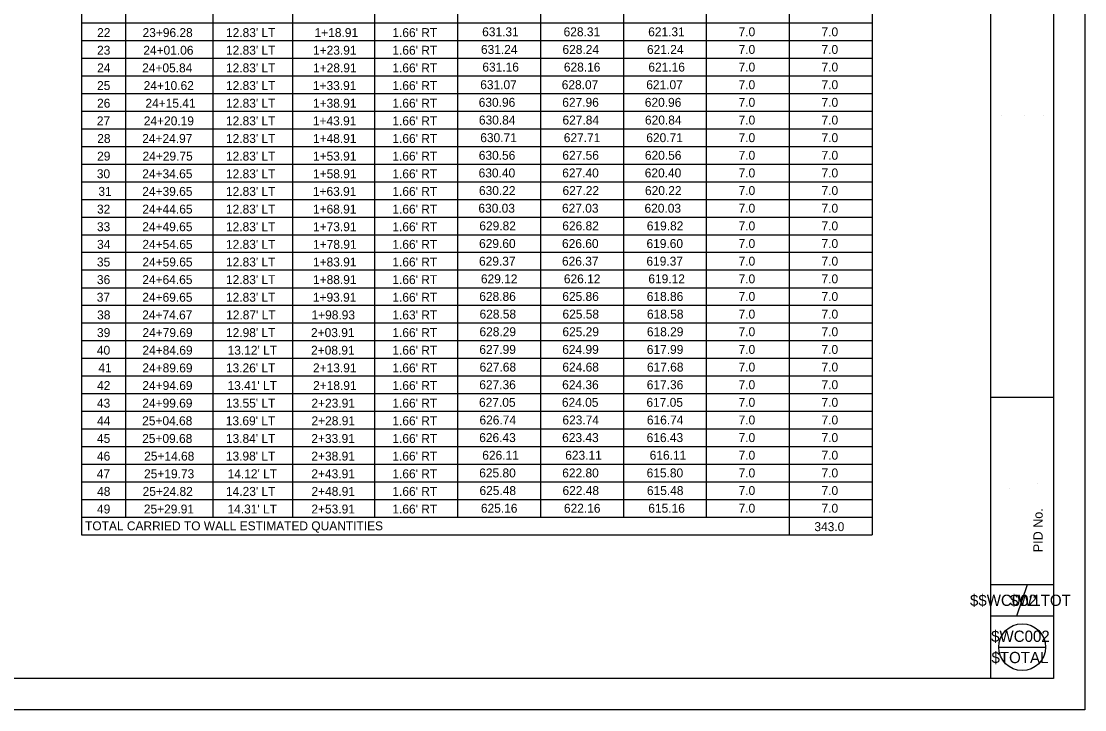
# Model space of a CAD drawing. Extents: x -0.2 to 33.8, y -0.1 to 21.9.
# Drawn here: x 16.78 to 33.78, y -0.13 to 10.88 of the extents above; entities that cross this region are included whole.
import ezdxf

# ---------------------------------------------------------------- set-up
doc = ezdxf.new("R2010")
doc.units = 0
for name, color, linetype in [('BR_P_Gen_Text', 7, 'Continuous'), ('SH_Border', 7, 'Continuous'), ('SH_Cut_Line', 7, 'Continuous'), ('SH_Data', 7, 'Continuous')]:
    doc.layers.add(name, color=color, linetype=linetype)

msp = doc.modelspace()

# ---------------------------------------------------------------- linework, layer by layer
at = {"layer": 'BR_P_Gen_Text'}
for p, q in [((17.738, 19.836), (17.738, 2.667)), ((30.379, 19.836), (30.379, 2.667)), ((18.444, 19.554), (18.444, 2.949)), ((19.84, 19.554), (19.84, 2.949)), ((21.11, 19.554), (21.11, 2.949)), ((22.422, 19.554), (22.422, 2.949)), ((23.748, 19.554), (23.748, 2.949)), ((25.074, 19.554), (25.074, 2.949)), ((26.4, 19.554), (26.4, 2.949)), ((27.726, 19.554), (27.726, 2.949)), ((29.052, 19.554), (29.052, 2.667)), ((17.738, 10.85), (30.379, 10.85)), ((17.738, 10.567), (30.379, 10.567)), ((17.738, 10.285), (30.379, 10.285)), ((17.738, 10.003), (30.379, 10.003)), ((17.738, 9.721), (30.379, 9.721)), ((17.738, 9.439), (30.379, 9.439)), ((17.738, 9.157), (30.379, 9.157)), ((17.738, 8.875), (30.379, 8.875)), ((17.738, 8.592), (30.379, 8.592)), ((17.738, 8.31), (30.379, 8.31)), ((17.738, 8.028), (30.379, 8.028)), ((17.738, 7.746), (30.379, 7.746)), ((17.738, 7.464), (30.379, 7.464)), ((17.738, 7.182), (30.379, 7.182)), ((17.738, 6.9), (30.379, 6.9)), ((17.738, 6.617), (30.379, 6.617)), ((17.738, 6.335), (30.379, 6.335)), ((17.738, 6.053), (30.379, 6.053)), ((17.738, 5.771), (30.379, 5.771)), ((17.738, 5.489), (30.379, 5.489)), ((17.738, 5.207), (30.379, 5.207)), ((17.738, 4.924), (30.379, 4.924)), ((17.738, 4.642), (30.379, 4.642)), ((17.738, 4.36), (30.379, 4.36)), ((17.738, 4.078), (30.379, 4.078)), ((17.738, 3.796), (30.379, 3.796)), ((17.738, 3.514), (30.379, 3.514)), ((17.738, 3.232), (30.379, 3.232)), ((17.738, 2.949), (30.379, 2.949)), ((17.738, 2.667), (30.379, 2.667))]:
    msp.add_line(p, q, dxfattribs=at)
at = {"layer": 'SH_Border'}
for p, q in [((32.275, 0.368), (32.275, 21.368)), ((32.275, 4.868), (33.275, 4.868)), ((32.275, 1.868), (33.275, 1.868)), ((32.692, 1.368), (32.859, 1.868)), ((32.275, 1.368), (33.275, 1.368))]:
    msp.add_line(p, q, dxfattribs=at)
msp.add_lwpolyline([(1.775, 21.368), (33.275, 21.368), (33.275, 0.368), (1.775, 0.368)], close=True, dxfattribs=at)
at = {"layer": 'SH_Cut_Line'}
msp.add_lwpolyline([(-0.225, 21.868), (33.775, 21.868), (33.775, -0.132), (-0.225, -0.132)], close=True, dxfattribs=at)
at = {"layer": 'SH_Data'}
for p, q in [((32.442, 9.368), (32.442, 9.368)), ((32.817, 9.368), (32.817, 9.368)), ((33.109, 9.368), (33.109, 9.368)), ((33.025, 3.486), (33.025, 3.486)), ((32.575, 3.398), (32.575, 3.398)), ((32.525, 1.618), (32.525, 1.618)), ((33.025, 1.618), (33.025, 1.618)), ((32.4, 0.868), (33.15, 0.868)), ((32.775, 0.953), (32.775, 0.953)), ((32.775, 0.613), (32.775, 0.613))]:
    msp.add_line(p, q, dxfattribs=at)
msp.add_circle((32.775, 0.868), 0.375, dxfattribs=at)

# ---------------------------------------------------------------- texts
at = {"layer": 'BR_P_Gen_Text'}
for s, height, p in [('22', 0.1428, (17.988, 10.624)), ('23+96.28', 0.1428, (18.714, 10.624)), ("12.83' LT", 0.1428, (20.048, 10.624)), ('1+18.91', 0.1428, (21.464, 10.624)), ("1.66' RT", 0.1428, (22.708, 10.624)), ('631.31', 0.1428, (24.143, 10.637)), ('628.31', 0.1428, (25.445, 10.637)), ('621.31', 0.1428, (26.797, 10.637)), ('7.0', 0.1428, (28.242, 10.637)), ('7.0', 0.1428, (29.568, 10.637)), ('23', 0.1428, (17.987, 10.342)), ('24+01.06', 0.1428, (18.726, 10.342)), ("12.83' LT", 0.1428, (20.048, 10.342)), ('1+23.91', 0.1428, (21.439, 10.342)), ("1.66' RT", 0.1428, (22.708, 10.342)), ('631.24', 0.1428, (24.124, 10.355)), ('628.24', 0.1428, (25.427, 10.355)), ('621.24', 0.1428, (26.778, 10.355)), ('7.0', 0.1428, (28.242, 10.355)), ('7.0', 0.1428, (29.568, 10.355)), ('24', 0.1428, (17.989, 10.06)), ('24+05.84', 0.1428, (18.708, 10.06)), ("12.83' LT", 0.1428, (20.048, 10.06)), ('1+28.91', 0.1428, (21.44, 10.06)), ("1.66' RT", 0.1428, (22.708, 10.06)), ('631.16', 0.1428, (24.146, 10.073)), ('628.16', 0.1428, (25.449, 10.073)), ('621.16', 0.1428, (26.8, 10.073)), ('7.0', 0.1428, (28.242, 10.073)), ('7.0', 0.1428, (29.568, 10.073)), ('25', 0.1428, (17.987, 9.777)), ('24+10.62', 0.1428, (18.732, 9.777)), ("12.83' LT", 0.1428, (20.048, 9.777)), ('1+33.91', 0.1428, (21.437, 9.777)), ("1.66' RT", 0.1428, (22.708, 9.777)), ('631.07', 0.1428, (24.112, 9.791)), ('628.07', 0.1428, (25.415, 9.791)), ('621.07', 0.1428, (26.766, 9.791)), ('7.0', 0.1428, (28.242, 9.791)), ('7.0', 0.1428, (29.568, 9.791)), ('26', 0.1428, (17.987, 9.495)), ('24+15.41', 0.1428, (18.76, 9.495)), ("12.83' LT", 0.1428, (20.048, 9.495)), ('1+38.91', 0.1428, (21.438, 9.495)), ("1.66' RT", 0.1428, (22.708, 9.495)), ('630.96', 0.1428, (24.088, 9.509)), ('627.96', 0.1428, (25.424, 9.509)), ('620.96', 0.1428, (26.743, 9.509)), ('7.0', 0.1428, (28.242, 9.509)), ('7.0', 0.1428, (29.568, 9.509)), ('27', 0.1428, (17.984, 9.213)), ('24+20.19', 0.1428, (18.734, 9.213)), ("12.83' LT", 0.1428, (20.048, 9.213)), ('1+43.91', 0.1428, (21.437, 9.213)), ("1.66' RT", 0.1428, (22.708, 9.213)), ('630.84', 0.1428, (24.091, 9.226)), ('627.84', 0.1428, (25.427, 9.226)), ('620.84', 0.1428, (26.746, 9.226)), ('7.0', 0.1428, (28.242, 9.226)), ('7.0', 0.1428, (29.568, 9.226)), ('28', 0.1428, (17.99, 8.931)), ('24+24.97', 0.1428, (18.709, 8.931)), ("12.83' LT", 0.1428, (20.048, 8.931)), ('1+48.91', 0.1428, (21.438, 8.931)), ("1.66' RT", 0.1428, (22.708, 8.931)), ('630.71', 0.1428, (24.113, 8.944)), ('627.71', 0.1428, (25.448, 8.944)), ('620.71', 0.1428, (26.767, 8.944)), ('7.0', 0.1428, (28.242, 8.944)), ('7.0', 0.1428, (29.568, 8.944)), ('29', 0.1428, (17.988, 8.649)), ('24+29.75', 0.1428, (18.714, 8.649)), ("12.83' LT", 0.1428, (20.048, 8.649)), ('1+53.91', 0.1428, (21.438, 8.649)), ("1.66' RT", 0.1428, (22.708, 8.649)), ('630.56', 0.1428, (24.089, 8.662)), ('627.56', 0.1428, (25.425, 8.662)), ('620.56', 0.1428, (26.744, 8.662)), ('7.0', 0.1428, (28.242, 8.662)), ('7.0', 0.1428, (29.568, 8.662)), ('30', 0.1428, (17.983, 8.367)), ('24+34.65', 0.1428, (18.71, 8.367)), ("12.83' LT", 0.1428, (20.048, 8.367)), ('1+58.91', 0.1428, (21.439, 8.367)), ("1.66' RT", 0.1428, (22.708, 8.367)), ('630.40', 0.1428, (24.087, 8.38)), ('627.40', 0.1428, (25.423, 8.38)), ('620.40', 0.1428, (26.742, 8.38)), ('7.0', 0.1428, (28.242, 8.38)), ('7.0', 0.1428, (29.568, 8.38)), ('31', 0.1428, (18.008, 8.085)), ('24+39.65', 0.1428, (18.71, 8.085)), ("12.83' LT", 0.1428, (20.048, 8.085)), ('1+63.91', 0.1428, (21.437, 8.085)), ("1.66' RT", 0.1428, (22.708, 8.085)), ('630.22', 0.1428, (24.092, 8.098)), ('627.22', 0.1428, (25.427, 8.098)), ('620.22', 0.1428, (26.746, 8.098)), ('7.0', 0.1428, (28.242, 8.098)), ('7.0', 0.1428, (29.568, 8.098)), ('32', 0.1428, (17.986, 7.802)), ('24+44.65', 0.1428, (18.711, 7.802)), ("12.83' LT", 0.1428, (20.048, 7.802)), ('1+68.91', 0.1428, (21.438, 7.802)), ("1.66' RT", 0.1428, (22.708, 7.802)), ('630.03', 0.1428, (24.083, 7.816)), ('627.03', 0.1428, (25.419, 7.816)), ('620.03', 0.1428, (26.738, 7.816)), ('7.0', 0.1428, (28.242, 7.816)), ('7.0', 0.1428, (29.568, 7.816)), ('33', 0.1428, (17.985, 7.52)), ('24+49.65', 0.1428, (18.71, 7.52)), ("12.83' LT", 0.1428, (20.048, 7.52)), ('1+73.91', 0.1428, (21.439, 7.52)), ("1.66' RT", 0.1428, (22.708, 7.52)), ('629.82', 0.1428, (24.098, 7.534)), ('626.82', 0.1428, (25.424, 7.534)), ('619.82', 0.1428, (26.775, 7.534)), ('7.0', 0.1428, (28.242, 7.534)), ('7.0', 0.1428, (29.568, 7.534)), ('34', 0.1428, (17.987, 7.238)), ('24+54.65', 0.1428, (18.711, 7.238)), ("12.83' LT", 0.1428, (20.048, 7.238)), ('1+78.91', 0.1428, (21.44, 7.238)), ("1.66' RT", 0.1428, (22.708, 7.238)), ('629.60', 0.1428, (24.094, 7.251)), ('626.60', 0.1428, (25.42, 7.251)), ('619.60', 0.1428, (26.77, 7.251)), ('7.0', 0.1428, (28.242, 7.251)), ('7.0', 0.1428, (29.568, 7.251)), ('35', 0.1428, (17.985, 6.956)), ('24+59.65', 0.1428, (18.711, 6.956)), ("12.83' LT", 0.1428, (20.048, 6.956)), ('1+83.91', 0.1428, (21.438, 6.956)), ("1.66' RT", 0.1428, (22.708, 6.956)), ('629.37', 0.1428, (24.093, 6.969)), ('626.37', 0.1428, (25.419, 6.969)), ('619.37', 0.1428, (26.769, 6.969)), ('7.0', 0.1428, (28.242, 6.969)), ('7.0', 0.1428, (29.568, 6.969)), ('36', 0.1428, (17.985, 6.674)), ('24+64.65', 0.1428, (18.71, 6.674)), ("12.83' LT", 0.1428, (20.048, 6.674)), ('1+88.91', 0.1428, (21.439, 6.674)), ("1.66' RT", 0.1428, (22.708, 6.674)), ('629.12', 0.1428, (24.123, 6.687)), ('626.12', 0.1428, (25.449, 6.687)), ('619.12', 0.1428, (26.8, 6.687)), ('7.0', 0.1428, (28.242, 6.687)), ('7.0', 0.1428, (29.568, 6.687)), ('37', 0.1428, (17.982, 6.392)), ('24+69.65', 0.1428, (18.71, 6.392)), ("12.83' LT", 0.1428, (20.048, 6.392)), ('1+93.91', 0.1428, (21.437, 6.392)), ("1.66' RT", 0.1428, (22.708, 6.392)), ('628.86', 0.1428, (24.097, 6.405)), ('625.86', 0.1428, (25.424, 6.405)), ('618.86', 0.1428, (26.774, 6.405)), ('7.0', 0.1428, (28.242, 6.405)), ('7.0', 0.1428, (29.568, 6.405)), ('38', 0.1428, (17.988, 6.11)), ('24+74.67', 0.1428, (18.709, 6.11)), ("12.87' LT", 0.1428, (20.05, 6.11)), ('1+98.93', 0.1428, (21.415, 6.11)), ("1.63' RT", 0.1428, (22.708, 6.11)), ('628.58', 0.1428, (24.101, 6.123)), ('625.58', 0.1428, (25.427, 6.123)), ('618.58', 0.1428, (26.777, 6.123)), ('7.0', 0.1428, (28.242, 6.123)), ('7.0', 0.1428, (29.568, 6.123)), ('39', 0.1428, (17.986, 5.827)), ('24+79.69', 0.1428, (18.712, 5.827)), ("12.98' LT", 0.1428, (20.048, 5.827)), ('2+03.91', 0.1428, (21.407, 5.827)), ("1.66' RT", 0.1428, (22.708, 5.827)), ('628.29', 0.1428, (24.1, 5.841)), ('625.29', 0.1428, (25.426, 5.841)), ('618.29', 0.1428, (26.776, 5.841)), ('7.0', 0.1428, (28.242, 5.841)), ('7.0', 0.1428, (29.568, 5.841)), ('40', 0.1428, (17.984, 5.545)), ('24+84.69', 0.1428, (18.712, 5.545)), ("13.12' LT", 0.1428, (20.074, 5.545)), ('2+08.91', 0.1428, (21.408, 5.545)), ("1.66' RT", 0.1428, (22.708, 5.545)), ('627.99', 0.1428, (24.098, 5.558)), ('624.99', 0.1428, (25.423, 5.558)), ('617.99', 0.1428, (26.775, 5.558)), ('7.0', 0.1428, (28.242, 5.558)), ('7.0', 0.1428, (29.568, 5.558)), ('41', 0.1428, (18.008, 5.263)), ('24+89.69', 0.1428, (18.711, 5.263)), ("13.26' LT", 0.1428, (20.047, 5.263)), ('2+13.91', 0.1428, (21.439, 5.263)), ("1.66' RT", 0.1428, (22.708, 5.263)), ('627.68', 0.1428, (24.101, 5.276)), ('624.68', 0.1428, (25.425, 5.276)), ('617.68', 0.1428, (26.777, 5.276)), ('7.0', 0.1428, (28.242, 5.276)), ('7.0', 0.1428, (29.568, 5.276)), ('42', 0.1428, (17.987, 4.981)), ('24+94.69', 0.1428, (18.711, 4.981)), ("13.41' LT", 0.1428, (20.072, 4.981)), ('2+18.91', 0.1428, (21.44, 4.981)), ("1.66' RT", 0.1428, (22.708, 4.981)), ('627.36', 0.1428, (24.097, 4.994)), ('624.36', 0.1428, (25.422, 4.994)), ('617.36', 0.1428, (26.774, 4.994)), ('7.0', 0.1428, (28.242, 4.994)), ('7.0', 0.1428, (29.568, 4.994)), ('43', 0.1428, (17.985, 4.699)), ('24+99.69', 0.1428, (18.71, 4.699)), ("13.55' LT", 0.1428, (20.047, 4.699)), ('2+23.91', 0.1428, (21.414, 4.699)), ("1.66' RT", 0.1428, (22.708, 4.699)), ('627.05', 0.1428, (24.093, 4.712)), ('624.05', 0.1428, (25.418, 4.712)), ('617.05', 0.1428, (26.769, 4.712)), ('7.0', 0.1428, (28.242, 4.712)), ('7.0', 0.1428, (29.568, 4.712)), ('44', 0.1428, (17.987, 4.417)), ('25+04.68', 0.1428, (18.708, 4.417)), ("13.69' LT", 0.1428, (20.045, 4.417)), ('2+28.91', 0.1428, (21.415, 4.417)), ("1.66' RT", 0.1428, (22.708, 4.417)), ('626.74', 0.1428, (24.1, 4.43)), ('623.74', 0.1428, (25.426, 4.43)), ('616.74', 0.1428, (26.776, 4.43)), ('7.0', 0.1428, (28.242, 4.43)), ('7.0', 0.1428, (29.568, 4.43)), ('45', 0.1428, (17.986, 4.134)), ('25+09.68', 0.1428, (18.708, 4.134)), ("13.84' LT", 0.1428, (20.047, 4.134)), ('2+33.91', 0.1428, (21.412, 4.134)), ("1.66' RT", 0.1428, (22.708, 4.134)), ('626.43', 0.1428, (24.096, 4.148)), ('623.43', 0.1428, (25.422, 4.148)), ('616.43', 0.1428, (26.772, 4.148)), ('7.0', 0.1428, (28.242, 4.148)), ('7.0', 0.1428, (29.568, 4.148)), ('46', 0.1428, (17.985, 3.852)), ('25+14.68', 0.1428, (18.74, 3.852)), ("13.98' LT", 0.1428, (20.046, 3.852)), ('2+38.91', 0.1428, (21.413, 3.852)), ("1.66' RT", 0.1428, (22.708, 3.852)), ('626.11', 0.1428, (24.145, 3.866)), ('623.11', 0.1428, (25.471, 3.866)), ('616.11', 0.1428, (26.821, 3.866)), ('7.0', 0.1428, (28.242, 3.866)), ('7.0', 0.1428, (29.568, 3.866)), ('47', 0.1428, (17.983, 3.57)), ('25+19.73', 0.1428, (18.738, 3.57)), ("14.12' LT", 0.1428, (20.074, 3.57)), ('2+43.91', 0.1428, (21.413, 3.57)), ("1.66' RT", 0.1428, (22.708, 3.57)), ('625.80', 0.1428, (24.096, 3.583)), ('622.80', 0.1428, (25.423, 3.583)), ('615.80', 0.1428, (26.772, 3.583)), ('7.0', 0.1428, (28.242, 3.583)), ('7.0', 0.1428, (29.568, 3.583)), ('48', 0.1428, (17.988, 3.288)), ('25+24.82', 0.1428, (18.715, 3.288)), ("14.23' LT", 0.1428, (20.048, 3.288)), ('2+48.91', 0.1428, (21.414, 3.288)), ("1.66' RT", 0.1428, (22.708, 3.288)), ('625.48', 0.1428, (24.1, 3.301)), ('622.48', 0.1428, (25.427, 3.301)), ('615.48', 0.1428, (26.777, 3.301)), ('7.0', 0.1428, (28.242, 3.301)), ('7.0', 0.1428, (29.568, 3.301)), ('49', 0.1428, (17.986, 3.006)), ('25+29.91', 0.1428, (18.735, 3.006)), ("14.31' LT", 0.1428, (20.072, 3.006)), ('2+53.91', 0.1428, (21.413, 3.006)), ("1.66' RT", 0.1428, (22.708, 3.006)), ('625.16', 0.1428, (24.123, 3.019)), ('622.16', 0.1428, (25.45, 3.019)), ('615.16', 0.1428, (26.799, 3.019)), ('7.0', 0.1428, (28.242, 3.019)), ('7.0', 0.1428, (29.568, 3.019)), ('TOTAL CARRIED TO WALL ESTIMATED QUANTITIES', 0.14277, (17.795, 2.737)), ('343.0', 0.1428, (29.454, 2.724))]:
    msp.add_text(s, height=height, dxfattribs=at).set_placement(p)
at = {"layer": 'SH_Data'}
for s, height, rotation, p in [('PID No.', 0.15, 90, (33.103, 2.387)), ('$$WC002', 0.18, 360, (31.941, 1.528)), ('$W1TOT', 0.18, 360, (32.577, 1.528)), ('$WC002', 0.18, 360, (32.279, 0.953)), ('$TOTAL', 0.18, 360, (32.285, 0.613))]:
    msp.add_text(s, height=height, rotation=rotation, dxfattribs=at).set_placement(p)

doc.saveas('drawing.dxf')
